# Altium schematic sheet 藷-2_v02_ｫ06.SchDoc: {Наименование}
size 420 x 297 mm; DrawnBy: Булычев; Engineer: {Инженер}; DocumentNumber: СИЭТ 21.02.110.000 Э3; SheetNumber: 6; SheetTotal: 6; Title1str: Плата управления; PageSetup: Record=PageOptions|CenterHorizontal=False|CenterVertical=False|PrintScale=0.95|XCorrection=1.00|YCorrection=1.00|PrintKind=2|BorderSize=5000000|LeftOffset=300|BottomOffset=0|Orientation=2|PaperLength=4200|PaperWidth=2970|Scale=100|PaperSource=15|PrintQuality=-1|MediaType=1|DitherType=10|PaperKind=ISO A3|PrintScaleMode=1; Title2str: (ПУ-2); EngineerName: {Инженер}; DocumentType: Схема электрическая принципиальная; DocumentType1str: {Документ}; DocumentType2str: {Документ}
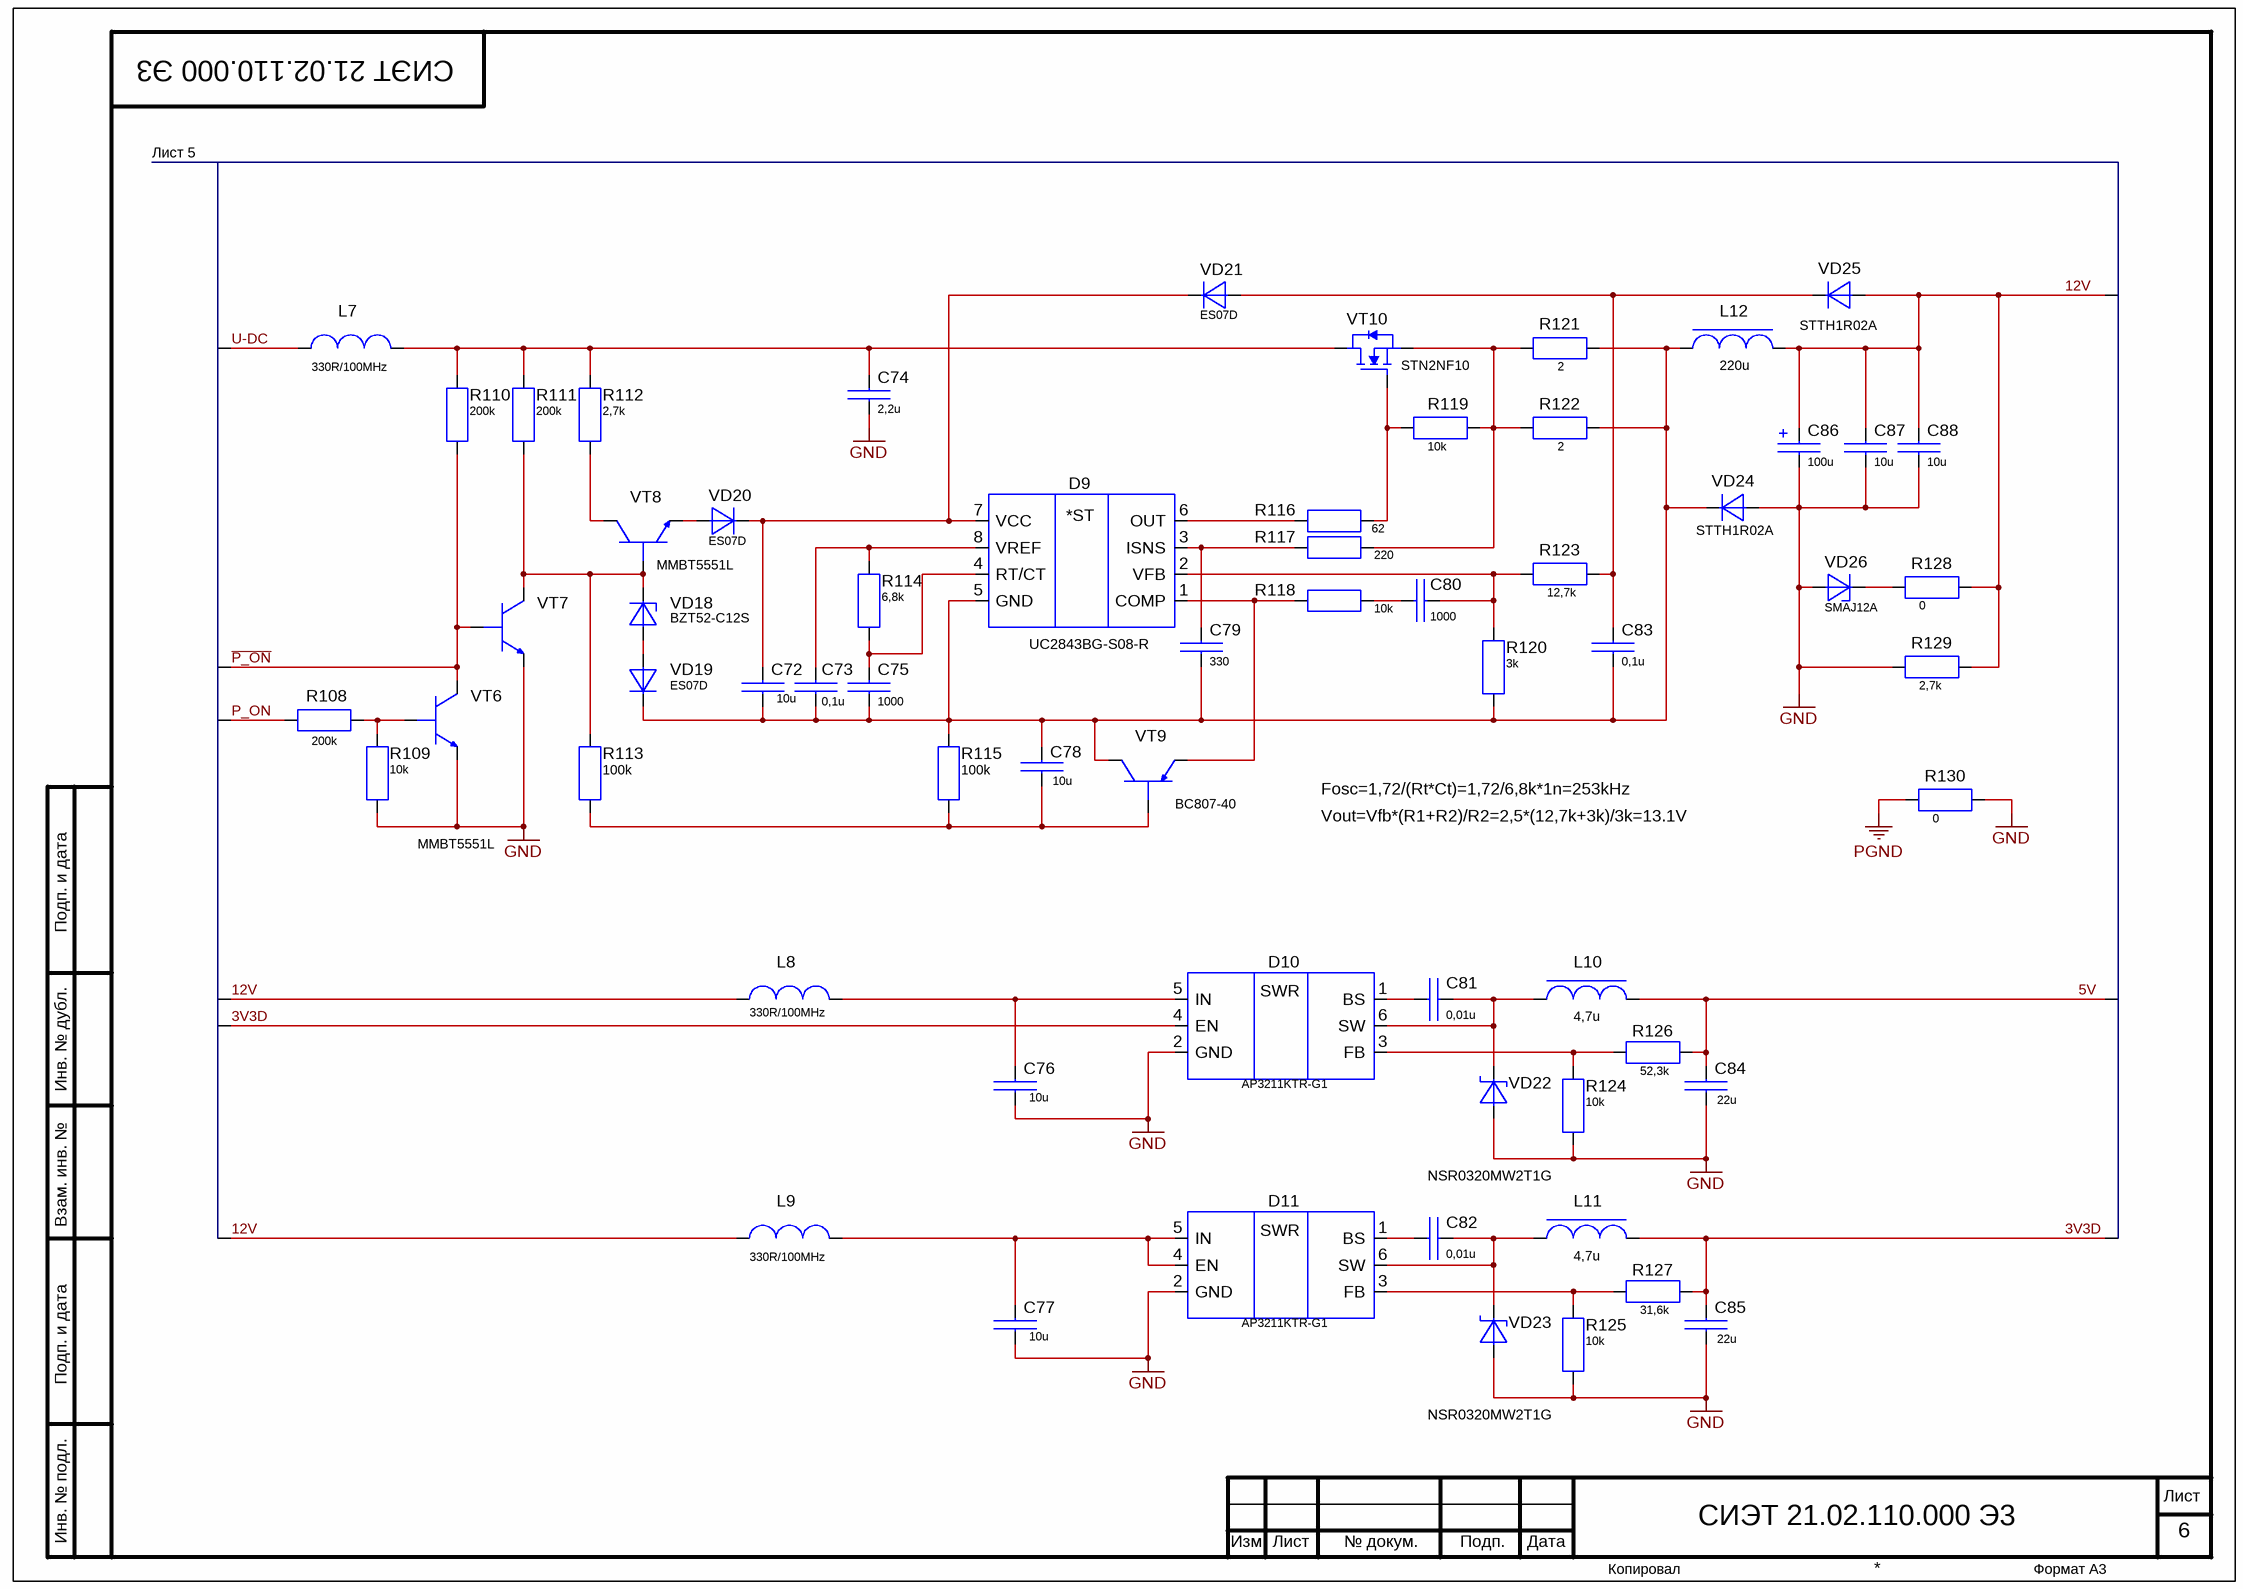
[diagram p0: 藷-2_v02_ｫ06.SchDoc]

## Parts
C72  value 10u  [1206]  (hidden comment: CL31A106KAHNNNE)
C73  value 0,1u  [0603]  (hidden comment: CL10B104KB8NNNC)
C74  value 2,2u  [1210]  (hidden comment: CL32B225KCJSNNE)
C75  value 1000  [0603]  (hidden comment: CL10C102JB8NNNC)
C76  value 10u  [1206]  (hidden comment: CL31A106KAHNNNE)
C77  value 10u  [1206]  (hidden comment: CL31A106KAHNNNE)
C78  value 10u  [0603]  (hidden comment: CL10A106MQ8NNNC)
C79  value 330  [0603]  (hidden comment: CL10C331JB8NNNC)
C80  value 1000  [0603]  (hidden comment: CL10C102JB8NNNC)
C81  value 0,01u  [0603]  (hidden comment: CL10B103KB8NNNC)
C82  value 0,01u  [0603]  (hidden comment: CL10B103KB8NNNC)
C83  value 0,1u  [0603]  (hidden comment: CL10B104KB8NNNC)
C84  value 22u  [1206]  (hidden comment: CL31A226MOCLNNC)
C85  value 22u  [1206]  (hidden comment: CL31A226MOCLNNC)
C86  value 100u  [6.3x11s]  (hidden comment: UHE1E101MED)
C87  value 10u  [1206]  (hidden comment: CL31A106KAHNNNE)
C88  value 10u  [1206]  (hidden comment: CL31A106KAHNNNE)
D9  UC2843BG-S08-R  [SOP-8]
D10  AP3211KTR-G1  [SOT23-6]
D11  AP3211KTR-G1  [SOT23-6]
L7  Impedance@100МHz: 330R/100MHz  [BLM18]  (hidden comment: BLM18PG331SN1D)
L8  Impedance@100МHz: 330R/100MHz  [BLM18]  (hidden comment: BLM18PG331SN1D)
L9  Impedance@100МHz: 330R/100MHz  [BLM18]  (hidden comment: BLM18PG331SN1D)
L10  value 4,7u  [SH3018]  (hidden comment: SH30184R7YL)
L11  value 4,7u  [SH3018]  (hidden comment: SH30184R7YL)
L12  value 220u  [SRR1050A]  (hidden comment: SRR1050A-221Y)
R108  value 200k  [RC0805]  (hidden comment: RC0805FR-07200KL)
R109  value 10k  [RC0603]  (hidden comment: RC0603FR-0710KL)
R110  value 200k  [RC0805]  (hidden comment: RC0805FR-07200KL)
R111  value 200k  [RC0805]  (hidden comment: RC0805FR-07200KL)
R112  value 2,7k  [RC0805]  (hidden comment: RC0805FR-072K7L)
R113  value 100k  [RC0603]  (hidden comment: RC0603FR-07100KL)
R114  value 6,8k  [RC0603]  (hidden comment: RC0603FR-076K8L)
R115  value 100k  [RC0603]  (hidden comment: RC0603FR-07100KL)
R116  value 62  [RC0603]  (hidden comment: RC0603FR-0762RL)
R117  value 220  [RC0603]  (hidden comment: RC0603FR-07220RL)
R118  value 10k  [RC0603]  (hidden comment: RC0603FR-0710KL)
R119  value 10k  [RC0603]  (hidden comment: RC0603FR-0710KL)
R120  value 3k  [RC0603]  (hidden comment: RC0603FR-073KL)
R121  value 2  [RC1206]  (hidden comment: RC1206JR-072RL)
R122  value 2  [RC1206]  (hidden comment: RC1206JR-072RL)
R123  value 12,7k  [RC0603]  (hidden comment: RC0603FR-0712K7L)
R124  value 10k  [RC0603]  (hidden comment: RC0603FR-0710KL)
R125  value 10k  [RC0603]  (hidden comment: RC0603FR-0710KL)
R126  value 52,3k  [RC0603]  (hidden comment: RC0603FR-0752K3L)
R127  value 31,6k  [RC0603]  (hidden comment: RC0603FR-0731K6L)
R128  value 0  [RC0603]  (hidden comment: RC0603JR-070RL)
R129  value 2,7k  [RC0805]  (hidden comment: RC0805FR-072K7L)
R130  value 0  [RC0603]  (hidden comment: RC0603JR-070RL)
VD18  BZT52-С12S  [SOD-323]
VD19  ES07D  [DO-219AB(SMF)]
VD20  ES07D  [DO-219AB(SMF)]
VD21  ES07D  [DO-219AB(SMF)]
VD22  NSR0320MW2T1G  [SOD-323]
VD23  NSR0320MW2T1G  [SOD-323]
VD24  STTH1R02A  [SMA/DO-214AC]
VD25  STTH1R02A  [SMA/DO-214AC]
VD26  SMAJ12A  [P4SMAJ18]
VT6  MMBT5551L  [SOT-23]
VT7  MMBT5551L  [SOT-23]  (value not drawn)
VT8  MMBT5551L  [SOT-23]
VT9  BC807-40  [SOT-23]
VT10  STN2NF10  [SOT223]

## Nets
GND: C74.1 C76.1 C77.1 C84.1 C85.1 C86.2 C87.1 C88.1 D10.2(GND) D11.2(GND) R109.1 R124.1 R125.1 R129.2 R130.1 VD22.2 VD23.2 VD24.2(A) VD26.2 VT6.2(E) VT7.2(E)
PGND: R130.2
3V3D: C85.2 D10.4(EN) L11.2 R127.1
5V: C84.2 L10.2 R126.1
12V: C86.1 C87.2 C88.2 L8.1 L9.1 L12.2 R128.1 R129.1 VD25.2(A)
~{P_ON}: R110.1 VT6.3(C) VT7.1(B)
P_ON: R108.2
U-DC: L7.1
NetC72_1: C72.1 C73.2 C75.1 C78.2 C79.1 C83.2 D9.5(GND) L12.1 R115.2 R120.1 R121.2 R122.2 VD19.1(C) VD24.1(C) VT9.3(C)
NetC72_2: C72.2 D9.7(VCC) VD20.1(C) VD21.1(C)
NetC73_1: C73.1 D9.8(VREF) R114.1
NetC74_2: C74.2 L7.2 R110.2 R111.2 R112.1 VT10.2(D)
NetC75_2: C75.2 D9.4(RT/CT) R114.2
NetC76_2: C76.2 D10.5(IN) L8.2
NetC77_2: C77.2 D11.4(EN) D11.5(IN) L9.2
NetC78_1: C78.1 R113.1 R115.1 VT9.1(B)
NetC79_2: C79.2 D9.3(ISNS) R117.2
NetC80_1: C80.1 D9.2(VFB) R120.2 R123.2
NetC80_2: C80.2 R118.1
NetC81_1: C81.1 D10.6(SW) L10.1 VD22.1
NetC81_2: C81.2 D10.1(BS)
NetC82_1: C82.1 D11.6(SW) L11.1 VD23.1
NetC82_2: C82.2 D11.1(BS)
NetC83_1: C83.1 R123.1 VD21.2(A) VD25.1(C)
NetD9_1: D9.1(COMP) R118.2 VT9.2(E)
NetD9_6: D9.6(OUT) R116.2
NetD10_3: D10.3(FB) R124.2 R126.2
NetD11_3: D11.3(FB) R125.2 R127.2
NetR108_1: R108.1 R109.2 VT6.1(B)
NetR111_1: R111.1 R113.2 VD18.1(C) VT7.3(C) VT8.1(B)
NetR112_2: R112.2 VT8.3(C)
NetR116_1: R116.1 R119.2 VT10.1(G)
NetR117_1: R117.1 R119.1 R121.1 R122.1 VT10.3(S)
NetR128_2: R128.2 VD26.1
NetVD18_2: VD18.2(A) VD19.2(A)
NetVD20_2: VD20.2(A) VT8.2(E)

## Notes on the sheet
- Лист 5
- Fosc=1,72/(Rt*Ct)=1,72/6,8k*1n=253kHz
- Vout=Vfb*(R1+R2)/R2=2,5*(12,7k+3k)/3k=13.1V

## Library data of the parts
C72 C76 C77 = CL31B104KCFNNNE: 1206, 100V, 0.1uF; Pdf: GeneralCapacitors_12022.pdf; Voltage: 25 В; Tolerance: ±10%; ТКЕ: X5R
C73 C83 = CL10B104KB8NNNC: 0603 - 50V - 0,1uF; Pdf: GeneralCapacitors_12022.pdf; Voltage: 50В; Type: CL10; Tolerance: ±10%; ТКЕ: X7R
C74 = CL32B106KBJNNNE: 1210 - 100V - 2,2uF; Pdf: HighCapacitanceCapacitors_12022.pdf; Voltage: 100В; Type: CL32; Tolerance: ±10%; ТКЕ: X7R
C75 C79 C80 = CL10C151JB8NNNC: 0603 - 50V - 150pF; Pdf: GeneralCapacitors_12022.pdf; Voltage: 50В; Tolerance: ±5%; ТКЕ: NP0
C78 = CL10A225KP8NNNC: 0603, 10V, 2.2uF; Pdf: GeneralCapacitors_12022.pdf; Voltage: 6,3В; Type: CL10; Tolerance: ±10%; ТКЕ: X5R
C81 C82 = CL10B103KB8NNNC: 0603 - 50V - 0,01uF; Pdf: GeneralCapacitors_12022.pdf; Voltage: 50В; Type: CL10; Tolerance: ±10%; ТКЕ: X7R
C84 C85 = CL31B226KPHNNNE: 1206, 16V, 22uF; Pdf: GeneralCapacitors_12022.pdf; Type: CL31; Tolerance: ±20%; ТКЕ: X5R
C86 = UHE1E101MED: 6.3x11 25V 100uF High Ripple Current Al. Cap.; Tolerance: ±20%; Корпус: 6,3x11; Type: UHE; Voltage: 25В; КД: 6,3x11 100мкФ 25В 20% (UHE1E101MED); Замена: EEUFR1E101
C87 C88 = CL31A106KAHNNNE: 1206, 25V, 10uF; Pdf: GeneralCapacitors_12022.pdf; Voltage: 25 В; Tolerance: ±10%; ТКЕ: X5R
D9 = UC2843BG-S08-R: Current-Mode PWM Controller; Замена 1: UC2843AD8TR; Замена 2: UC2843AQD8RQ1
D10 D11 = AP3211KTR-G1: 4.5 V to 18 V Input, 1.4MHz, 1.5A DC-DC Buck Converter; Type: AP3211; Корпус: SOT-23-6; Замена: AOZ1280CI
L7-L9 = BLM18PG331SN1D: EMI Suppression Filter; Корпус: 0603; Pdf: Murata BLM.pdf; DCResistance: 0.15
L10 L11 = SH30184R7YL: Катушка индуктивности; Корпус: 3.8x3.8; Pdf: SH3018.pdf; Замена: SRR3818A-4R7Y
L12 = SRR1050A: Катушка индуктивности; Корпус: 10x10x5; Pdf: SRR1050A.pdf; Замена 1: SU1050221YF; Замена 2: CDRH105RNP-221NC; Замена 3: 7447714221; Замена 4: SCRH105RY-221
R108 R110-R112 R129 = RC0805: 0805, 0.125W, Thick Film Chip Resistors; Power: 0,125 Вт; Tolerance: ±1%; Pdf: RC0805.pdf; Корпус: 0805; ТКС: ±100 ppm/K
R109 R113-R120 R123-R127 = RC0603: 0603, 0.1W, Thick Film Chip Resistors; Power: 0,1 Вт; Tolerance: ±1%; Pdf: RC0603.pdf; Корпус: 0603; ТКС: ±100 ppm/K
R121 R122 = RC1206: 1206, 0.25W, Thick Film Chip Resistors; Power: 0,25 Вт; Tolerance: ±5%; Pdf: RC1206.pdf; Корпус: 1206; ТКС: ±100 ppm/K
R128 R130 = RC0603: 0603, 0.1W, Thick Film Chip Resistors; Power: 0,1 Вт; Tolerance: ±5%; Pdf: RC0603.pdf; Корпус: 0603; ТКС: ±100 ppm/K
VD18 = BZT52: SURFACE Stabilitron; Pdf: BZT52.pdf
VD19-VD21 = ES07D: Ultrafast Rectifier; Pdf: es07b.pdf; КД: ES07D-GS08
VD22 VD23 = NSR0320MW2T1: 20V 1A Schottky Barrier Diodes; Pdf: NSR0320MW2T1.pdf; Исполнение: Диод
VD24 VD25 = STTH1R02A: Ultrafast recovery diode; Pdf: STTH1R02.pdf; Корпус: SMA; Замена 1: STPS2H100A; Замена 2: ES1B
VD26 = P4SMAJ18: Transient Volnage Supressor Power 400 W; Pdf: p4smaj.pdf; Type: P4SMAJ18A; Корпус: SMA; Замена 1: P4SMAJ11A; Замена 2: 1SMA5929BT3G
VT6-VT8 = MMBT5551L: 300V NPN High Voltage Transistors; Type: MMBT5551LT1G; Pdf: MMBT5551LT1G.PDF; Замена 1: FMMT497TA; Замена 2: MMBTA42LT1G
VT9 = BC807-40: 45 V, 500 mA PNP general-purpose transistor; Pdf: BC807_BC807W_BC327.pdf
VT10 = DMN10H120SE: 100V N-Channel MOSFET; Pdf: DMN10H120SE.pdf; КД: DMN10H120SE-13; Доп. информация: Gate - Затвор, Drain - Сток, Source - Исток; Замена 2: UTT6N10ZG-AA3-R; Замена 3: TSM950N10CWRPG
